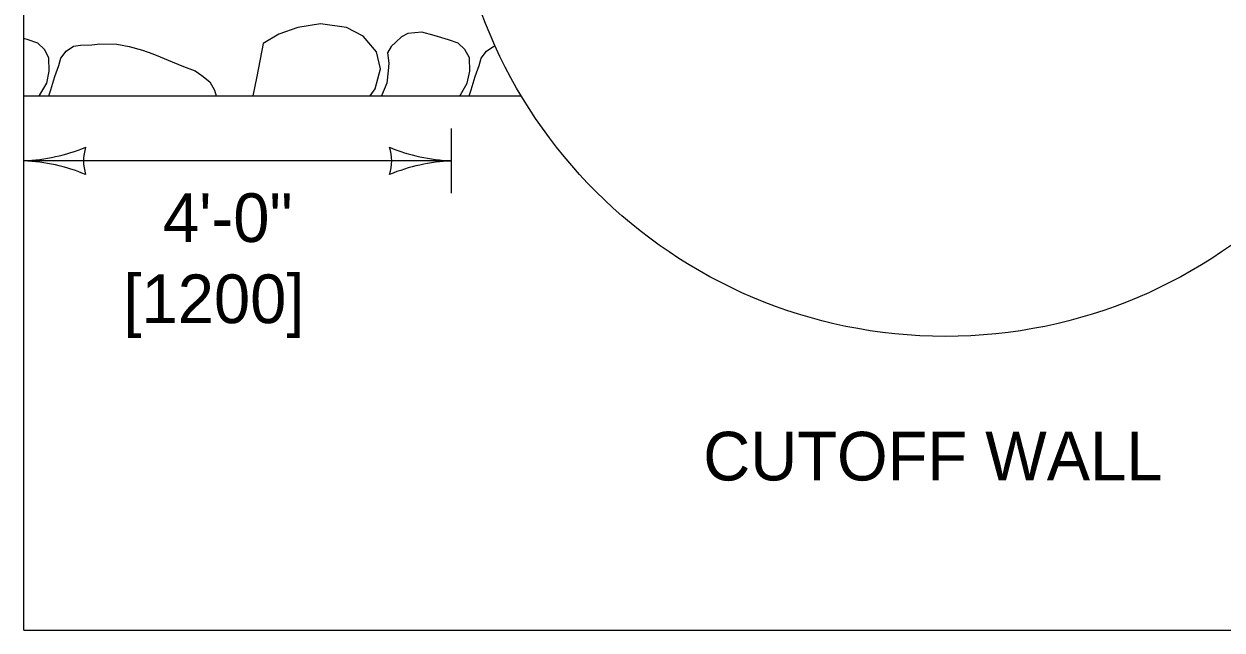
# Model space of a CAD drawing. Extents: x 49991.4 to 50021, y 49987.6 to 50011.4.
# Drawn here: x 50005.647 to 50007.124, y 50007.835 to 50008.582 of the extents above; entities that cross this region are included whole.
import ezdxf

# ---------------------------------------------------------------- set-up
doc = ezdxf.new("R2010")
doc.units = 0
for name, color, linetype in [('Default', 7, 'Continuous'), ('Level 1', 7, 'Continuous'), ('Level 2', 7, 'Continuous'), ('Level 3', 7, 'Continuous')]:
    doc.layers.add(name, color=color, linetype=linetype)

msp = doc.modelspace()

# ---------------------------------------------------------------- linework, layer by layer
at = {"layer": 'Default'}
for points in [[(50006.0741, 50008.4934), (50006.0802, 50008.5023), (50006.0868, 50008.5269), (50006.0819, 50008.5478), (50006.0654, 50008.5672), (50006.0449, 50008.5776), (50006.0129, 50008.5821), (50005.985, 50008.5776), (50005.9612, 50008.5694), (50005.9422, 50008.5579), (50005.9341, 50008.5172), (50005.9293, 50008.4934)], [(50006.1841, 50008.4934), (50006.1851, 50008.4948), (50006.1937, 50008.5093), (50006.1966, 50008.5239), (50006.1962, 50008.5403), (50006.1908, 50008.5508), (50006.1826, 50008.5586), (50006.1707, 50008.5627), (50006.1527, 50008.5679), (50006.1375, 50008.572), (50006.1202, 50008.5702), (50006.1124, 50008.5664), (50006.1055, 50008.5597), (50006.0997, 50008.5545), (50006.0952, 50008.5467), (50006.0968, 50008.5336), (50006.096, 50008.5243), (50006.0944, 50008.509), (50006.0878, 50008.4937), (50006.0878, 50008.4934)], [(50005.6658, 50008.4934), (50005.6668, 50008.4948), (50005.6754, 50008.5093), (50005.6783, 50008.5239), (50005.6779, 50008.5403), (50005.6726, 50008.5508), (50005.6644, 50008.5586), (50005.6525, 50008.5627), (50005.6473, 50008.5642)], [(50005.6779, 50008.4934), (50005.6803, 50008.5008), (50005.6853, 50008.5173), (50005.6902, 50008.5311), (50005.6926, 50008.54), (50005.6992, 50008.5486), (50005.7082, 50008.5549), (50005.7169, 50008.5561), (50005.7308, 50008.5564), (50005.7407, 50008.5576), (50005.7616, 50008.5572), (50005.7768, 50008.5542), (50005.7932, 50008.5497), (50005.8063, 50008.5452), (50005.8153, 50008.5415), (50005.8301, 50008.5355), (50005.8441, 50008.5296), (50005.8584, 50008.5243), (50005.8666, 50008.5187), (50005.8765, 50008.5109), (50005.8822, 50008.5005), (50005.8841, 50008.4934)], [(50006.1961, 50008.4934), (50006.1986, 50008.5008), (50006.2035, 50008.5173), (50006.2084, 50008.5311), (50006.2109, 50008.54), (50006.2175, 50008.5486), (50006.2265, 50008.5549), (50006.228, 50008.5551)]]:
    msp.add_lwpolyline(points, dxfattribs=at)
at = {"layer": 'Level 1'}
for p, q in [((50005.6473, 50007.8352), (50005.6473, 50009.6783)), ((50005.6473, 50008.4934), (50006.2603, 50008.4934)), ((50005.6473, 50007.8352), (50007.9186, 50007.8352))]:
    msp.add_line(p, q, dxfattribs=at)
msp.add_circle((50006.7828, 50008.8061), 0.609, dxfattribs=at)
at = {"layer": 'Level 3'}
for p, q in [((50006.1739, 50008.4534), (50006.1739, 50008.3734)), ((50006.1739, 50008.4134), (50005.6473, 50008.4134))]:
    msp.add_line(p, q, dxfattribs=at)
for centre, radius, start, end in [((50005.6358, 50008.6461), 0.233, 272.8273, 292.0772), ((50005.7755, 50008.4134), 0.0548, 162.1388, 197.8612), ((50006.1831, 50008.6355), 0.2223, 247.456, 267.6395), ((50006.0457, 50008.4134), 0.0548, 342.1388, 17.8612), ((50005.6381, 50008.1913), 0.2223, 67.456, 87.6395), ((50006.1854, 50008.1807), 0.233, 92.8273, 112.0772)]:
    msp.add_arc(centre, radius, start, end, dxfattribs=at)

# ---------------------------------------------------------------- texts
at = {"layer": 'Level 2'}
for s, p in [('4\'-0"', (50005.8186, 50008.3134)), ('[1200]', (50005.7699, 50008.2134)), ('CUTOFF WALL', (50006.4844, 50008.0195))]:
    msp.add_text(s, height=0.06, dxfattribs=at).set_placement(p)

doc.saveas('drawing.dxf')
